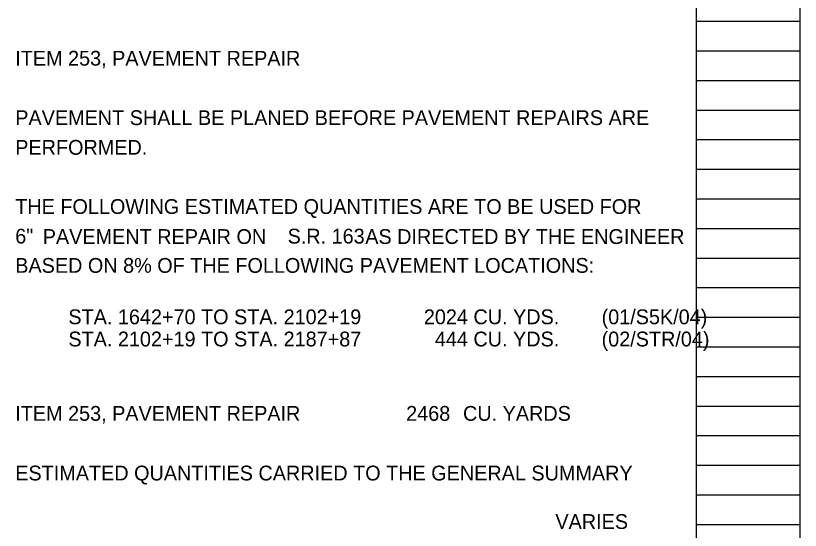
# Model space of a CAD drawing. Extents: x 0 to 34, y 0 to 22.
# Drawn here: x 17.24 to 24.66, y 6.24 to 11.11 of the extents above; entities that cross this region are included whole.
import ezdxf

# ---------------------------------------------------------------- set-up
doc = ezdxf.new("R2010")
doc.units = 0
doc.layers.add('SH_Data', color=7, linetype='Continuous')
doc.layers.add('TX_P_1', color=7, linetype='Continuous')

msp = doc.modelspace()

# ---------------------------------------------------------------- linework, layer by layer
at = {"layer": 'SH_Data'}
for p, q in [((23.68, 0.98), (23.68, 21.14)), ((24.66, 0.98), (24.66, 21.14)), ((23.68, 11.06), (24.66, 11.06)), ((23.68, 10.78), (24.66, 10.78)), ((23.68, 10.5), (24.66, 10.5)), ((23.68, 10.22), (24.66, 10.22)), ((23.68, 9.94), (24.66, 9.94)), ((23.68, 9.66), (24.66, 9.66)), ((23.68, 9.38), (24.66, 9.38)), ((23.68, 9.1), (24.66, 9.1)), ((23.68, 8.82), (24.66, 8.82)), ((23.68, 8.54), (24.66, 8.54)), ((23.68, 8.26), (24.66, 8.26)), ((23.68, 7.98), (24.66, 7.98)), ((23.68, 7.7), (24.66, 7.7)), ((23.68, 7.42), (24.66, 7.42)), ((23.68, 7.14), (24.66, 7.14)), ((23.68, 6.86), (24.66, 6.86)), ((23.68, 6.58), (24.66, 6.58)), ((23.68, 6.3), (24.66, 6.3))]:
    msp.add_line(p, q, dxfattribs=at)

# ---------------------------------------------------------------- texts
at = {"layer": 'TX_P_1'}
for s, p in [('ITEM 253, PAVEMENT REPAIR', (17.24, 10.64)), ('PAVEMENT SHALL BE PLANED BEFORE PAVEMENT REPAIRS ARE', (17.24, 10.0776)), ('PERFORMED.', (17.24, 9.7969)), ('THE FOLLOWING ESTIMATED QUANTITIES ARE TO BE USED FOR', (17.24, 9.2369)), ('6"', (17.24, 8.9569)), ('     PAVEMENT REPAIR ON                  AS DIRECTED BY THE ENGINEER', (17.24, 8.953)), ('S.R. 163', (19.8142, 8.9569)), ('BASED ON 8% OF THE FOLLOWING PAVEMENT LOCATIONS:', (17.24, 8.68)), ('STA. 1642+70 TO STA. 2102+19', (17.742, 8.1937)), ('2024 CU. YDS.', (21.102, 8.1937)), ('(01/S5K/04)', (22.782, 8.1937)), ('STA. 2102+19 TO STA. 2187+87', (17.742, 7.9837)), ('  444 CU. YDS.', (21.102, 7.9837)), ('(02/STR/04)', (22.782, 7.9837)), ('ITEM 253, PAVEMENT REPAIR         ', (17.24, 7.28)), ('2468', (20.9347, 7.28)), ('      CU. YARDS', (21.16, 7.28)), ('ESTIMATED QUANTITIES CARRIED TO THE GENERAL SUMMARY', (17.24, 6.7157)), ('VARIES', (22.3453, 6.2568))]:
    msp.add_text(s, height=0.14, dxfattribs=at).set_placement(p)

doc.saveas('drawing.dxf')
